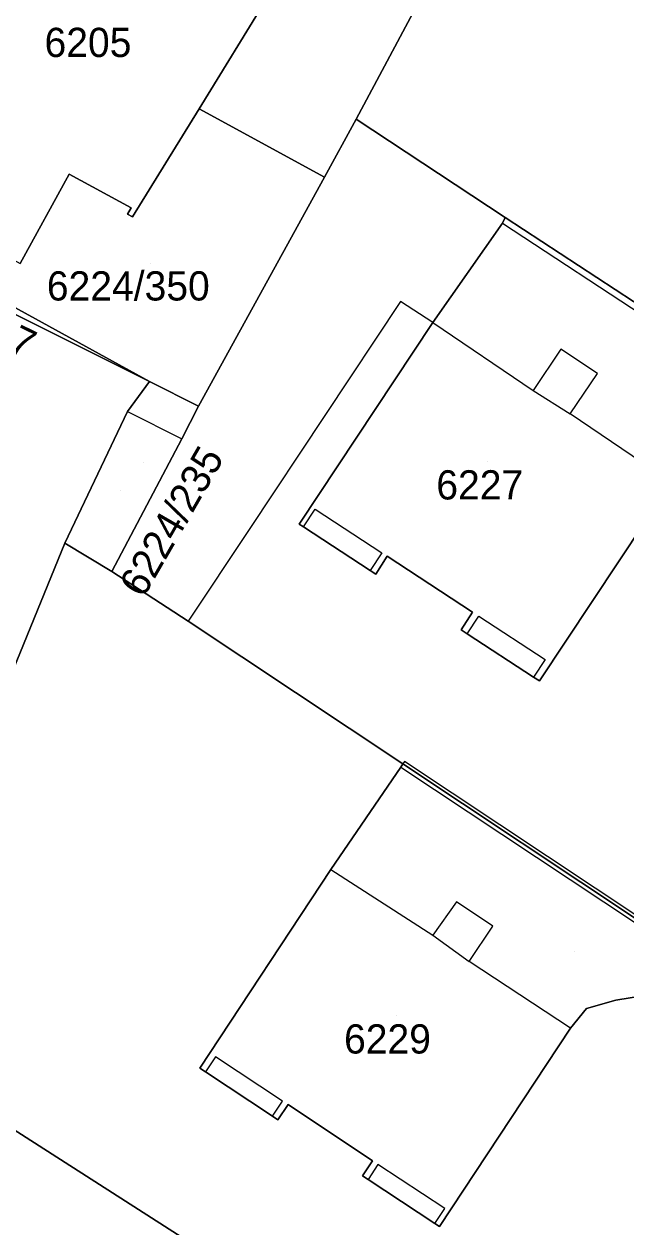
# Model space of a CAD drawing. Extents: x -266199 to -261993, y -1239047 to -1235108.
# Drawn here: x -263819.5 to -263778.3, y -1236358.3 to -1236276 of the extents above; entities that cross this region are included whole.
import ezdxf

# ---------------------------------------------------------------- set-up
doc = ezdxf.new("R2010")
doc.units = 0
for name, color, linetype in [('body_kn', 7, 'Continuous'), ('kladpar_druhypozemkov', 7, 'Continuous'), ('kladpar_hranice', 7, 'Continuous'), ('kladpar_parcelnecisla', 7, 'Continuous'), ('kladpar_plochy', 7, 'Continuous'), ('kladpar_sipky', 7, 'Continuous'), ('zappar_hrandruhpozemk', 7, 'Continuous')]:
    doc.layers.add(name, color=color, linetype=linetype)

msp = doc.modelspace()

# ---------------------------------------------------------------- linework, layer by layer
at = {"layer": 'body_kn'}
for p, q in [((-263807.51, -1236281.78), (-263807.51, -1236281.78)), ((-263796.75, -1236282.5), (-263796.75, -1236282.5)), ((-263796.75, -1236282.5), (-263796.75, -1236282.5)), ((-263816.41, -1236286.25), (-263816.41, -1236286.25)), ((-263798.93, -1236286.46), (-263798.93, -1236286.46)), ((-263798.93, -1236286.46), (-263798.93, -1236286.46)), ((-263812.41, -1236289), (-263812.41, -1236289)), ((-263812.17, -1236288.56), (-263812.17, -1236288.56)), ((-263812.06, -1236289.19), (-263812.06, -1236289.19)), ((-263786.56, -1236289.23), (-263786.56, -1236289.23)), ((-263786.73, -1236289.62), (-263786.73, -1236289.62)), ((-263786.73, -1236289.62), (-263786.73, -1236289.62)), ((-263793.71, -1236294.97), (-263793.71, -1236294.97)), ((-263791.51, -1236296.42), (-263791.51, -1236296.42)), ((-263791.51, -1236296.42), (-263791.51, -1236296.42)), ((-263782.73, -1236298.23), (-263782.73, -1236298.23)), ((-263780.23, -1236299.91), (-263780.23, -1236299.91)), ((-263810.9, -1236300.45), (-263810.9, -1236300.45)), ((-263810.9, -1236300.45), (-263810.9, -1236300.45)), ((-263784.64, -1236301.08), (-263784.64, -1236301.08)), ((-263784.64, -1236301.08), (-263784.64, -1236301.08)), ((-263812.41, -1236302.51), (-263812.41, -1236302.51)), ((-263812.41, -1236302.51), (-263812.41, -1236302.51)), ((-263807.56, -1236302.15), (-263807.56, -1236302.15)), ((-263782.09, -1236302.67), (-263782.09, -1236302.67)), ((-263808.68, -1236304.39), (-263808.68, -1236304.39)), ((-263799.56, -1236309.2), (-263799.56, -1236309.2)), ((-263804.09, -1236310.59), (-263804.09, -1236310.59)), ((-263800.66, -1236310.21), (-263800.66, -1236310.21)), ((-263800.35, -1236310.41), (-263800.35, -1236310.41)), ((-263816.7, -1236311.53), (-263816.7, -1236311.53)), ((-263795, -1236312.18), (-263795, -1236312.18)), ((-263794.62, -1236312.42), (-263794.62, -1236312.42)), ((-263813.49, -1236313.46), (-263813.49, -1236313.46)), ((-263813.49, -1236313.46), (-263813.49, -1236313.46)), ((-263795.79, -1236313.39), (-263795.79, -1236313.39)), ((-263795.79, -1236313.39), (-263795.79, -1236313.39)), ((-263795.41, -1236313.64), (-263795.41, -1236313.64)), ((-263788.78, -1236316.24), (-263788.78, -1236316.24)), ((-263788.36, -1236316.51), (-263788.36, -1236316.51)), ((-263808.25, -1236316.86), (-263808.25, -1236316.86)), ((-263789.57, -1236317.45), (-263789.57, -1236317.45)), ((-263789.15, -1236317.72), (-263789.15, -1236317.72)), ((-263783.81, -1236319.48), (-263783.81, -1236319.48)), ((-263784.6, -1236320.69), (-263784.6, -1236320.69)), ((-263784.6, -1236320.69), (-263784.6, -1236320.69)), ((-263784.21, -1236320.95), (-263784.21, -1236320.95)), ((-263793.69, -1236326.86), (-263793.69, -1236326.86)), ((-263793.69, -1236326.86), (-263793.69, -1236326.86)), ((-263793.55, -1236326.63), (-263793.55, -1236326.63)), ((-263793.45, -1236326.46), (-263793.45, -1236326.46)), ((-263798.48, -1236333.85), (-263798.48, -1236333.85)), ((-263798.48, -1236333.85), (-263798.48, -1236333.85)), ((-263789.89, -1236336.08), (-263789.89, -1236336.08)), ((-263787.4, -1236337.73), (-263787.4, -1236337.73)), ((-263791.51, -1236338.36), (-263791.51, -1236338.36)), ((-263791.51, -1236338.36), (-263791.51, -1236338.36)), ((-263789.01, -1236340.16), (-263789.01, -1236340.16)), ((-263789.01, -1236340.16), (-263789.01, -1236340.16)), ((-263778.97, -1236342.8), (-263778.97, -1236342.8)), ((-263780.98, -1236343.37), (-263780.98, -1236343.37)), ((-263782.08, -1236344.73), (-263782.08, -1236344.73)), ((-263782.08, -1236344.73), (-263782.08, -1236344.73)), ((-263806.39, -1236346.68), (-263806.39, -1236346.68)), ((-263807.45, -1236347.47), (-263807.45, -1236347.47)), ((-263807.07, -1236347.72), (-263807.07, -1236347.72)), ((-263807.07, -1236347.72), (-263807.07, -1236347.72)), ((-263801.8, -1236349.71), (-263801.8, -1236349.71)), ((-263801.42, -1236349.95), (-263801.42, -1236349.95)), ((-263802.49, -1236350.75), (-263802.49, -1236350.75)), ((-263802.11, -1236351), (-263802.11, -1236351)), ((-263795.63, -1236353.8), (-263795.63, -1236353.8)), ((-263795.26, -1236354.05), (-263795.26, -1236354.05)), ((-263796.31, -1236354.83), (-263796.31, -1236354.83)), ((-263795.94, -1236355.08), (-263795.94, -1236355.08)), ((-263795.94, -1236355.08), (-263795.94, -1236355.08)), ((-263790.69, -1236357.07), (-263790.69, -1236357.07)), ((-263791.36, -1236358.1), (-263791.36, -1236358.1)), ((-263791.04, -1236358.31), (-263791.04, -1236358.31))]:
    msp.add_line(p, q, dxfattribs=at)
at = {"layer": 'kladpar_druhypozemkov'}
for p, q in [((-263810.83, -1236292.41), (-263810.83, -1236292.41)), ((-263787.74, -1236305.93), (-263787.74, -1236305.93)), ((-263812.92, -1236307.92), (-263812.92, -1236307.92)), ((-263781.77, -1236339.49), (-263781.77, -1236339.49)), ((-263794.01, -1236343.86), (-263794.01, -1236343.86))]:
    msp.add_line(p, q, dxfattribs=at)
at = {"layer": 'kladpar_hranice'}
for p, q in [((-263810.9, -1236300.45), (-263846.39, -1236282.72)), ((-263800.35, -1236310.41), (-263795.79, -1236313.39)), ((-263795.79, -1236313.39), (-263800.35, -1236310.41)), ((-263789.15, -1236317.72), (-263784.6, -1236320.69)), ((-263784.6, -1236320.69), (-263789.15, -1236317.72)), ((-263807.07, -1236347.72), (-263802.49, -1236350.75)), ((-263802.49, -1236350.75), (-263807.07, -1236347.72)), ((-263795.94, -1236355.08), (-263791.36, -1236358.1)), ((-263791.36, -1236358.1), (-263795.94, -1236355.08))]:
    msp.add_line(p, q, dxfattribs=at)
for points in [[(-263796.75, -1236282.5), (-263788.43, -1236266.89), (-263783.8, -1236258.27), (-263775.41, -1236246.66), (-263764.02, -1236230.89), (-263749.03, -1236253.95), (-263754.73, -1236264.56), (-263764.22, -1236259.99), (-263768.57, -1236267.16), (-263777.59, -1236280.96), (-263777.22, -1236281.21)], [(-263798.93, -1236286.46), (-263807.51, -1236281.78), (-263802.82, -1236274.14), (-263803.17, -1236273.91), (-263803.44, -1236274.35), (-263807.6, -1236272.02), (-263804.25, -1236265.93), (-263807.98, -1236263.87), (-263806.58, -1236261.49), (-263804.15, -1236257.35), (-263788.43, -1236266.89), (-263796.75, -1236282.5), (-263798.93, -1236286.46)], [(-263822.7, -1236271.16), (-263819.28, -1236264.87), (-263818.87, -1236265.09), (-263819.18, -1236265.67), (-263814.21, -1236268.37), (-263810.89, -1236262.27), (-263807.98, -1236263.87), (-263804.25, -1236265.93), (-263807.6, -1236272.02), (-263803.44, -1236274.35), (-263803.17, -1236273.91), (-263802.82, -1236274.14), (-263807.51, -1236281.78), (-263812.06, -1236289.19), (-263812.41, -1236289), (-263812.17, -1236288.56), (-263816.41, -1236286.25), (-263819.76, -1236292.38)], [(-263761.6, -1236291.64), (-263761.29, -1236291.85), (-263752.18, -1236278.07), (-263747.42, -1236267.12), (-263740.96, -1236268.86), (-263740.08, -1236270.96), (-263745.67, -1236293.91), (-263749.42, -1236308.46), (-263754.6, -1236309.83), (-263770.22, -1236299.9), (-263786.56, -1236289.23), (-263796.75, -1236282.5)], [(-263846.39, -1236282.72), (-263845.64, -1236281.4), (-263832.11, -1236288.82), (-263824.25, -1236293.13), (-263810.9, -1236300.45)], [(-263824.25, -1236293.13), (-263822.95, -1236290.64), (-263819.76, -1236292.38), (-263816.41, -1236286.25), (-263812.17, -1236288.56), (-263812.41, -1236289), (-263812.06, -1236289.19), (-263807.51, -1236281.78), (-263798.93, -1236286.46), (-263807.56, -1236302.15), (-263810.9, -1236300.45), (-263824.25, -1236293.13)], [(-263857.92, -1236304.91), (-263846.39, -1236282.72), (-263810.9, -1236300.45)], [(-263813.49, -1236313.46), (-263808.68, -1236304.39), (-263807.56, -1236302.15), (-263798.93, -1236286.46), (-263796.75, -1236282.5), (-263786.56, -1236289.23), (-263786.73, -1236289.62), (-263791.51, -1236296.42), (-263800.66, -1236310.21), (-263800.35, -1236310.41)], [(-263791.51, -1236296.42), (-263786.73, -1236289.62), (-263786.56, -1236289.23), (-263770.22, -1236299.9), (-263754.6, -1236309.83), (-263749.42, -1236308.46), (-263752.65, -1236320.75), (-263756.67, -1236313.9), (-263770.56, -1236305.23), (-263772.57, -1236305.43), (-263774.56, -1236306.29), (-263775.19, -1236307.37), (-263784.21, -1236320.95), (-263784.6, -1236320.69)], [(-263800.35, -1236310.41), (-263800.66, -1236310.21), (-263791.51, -1236296.42)], [(-263810.9, -1236300.45), (-263812.41, -1236302.51), (-263816.7, -1236311.53), (-263821.43, -1236323.05), (-263857.92, -1236304.91)], [(-263813.49, -1236313.46), (-263816.7, -1236311.53), (-263812.41, -1236302.51), (-263810.9, -1236300.45), (-263807.56, -1236302.15), (-263808.68, -1236304.39), (-263813.49, -1236313.46)], [(-263784.6, -1236320.69), (-263784.21, -1236320.95), (-263775.19, -1236307.37), (-263774.56, -1236306.29), (-263772.57, -1236305.43), (-263770.56, -1236305.23), (-263756.67, -1236313.9), (-263752.65, -1236320.75), (-263759.07, -1236345.06), (-263763.77, -1236346.42), (-263777.28, -1236337.44), (-263793.55, -1236326.63), (-263808.25, -1236316.86), (-263813.49, -1236313.46)], [(-263762.85, -1236355.68), (-263773.1, -1236380.05), (-263777.22, -1236379.94), (-263805.43, -1236361.14), (-263826.5, -1236347.64), (-263830.59, -1236345.33), (-263821.43, -1236323.05), (-263816.7, -1236311.53), (-263813.49, -1236313.46), (-263808.25, -1236316.86), (-263793.55, -1236326.63), (-263793.69, -1236326.86), (-263798.48, -1236333.85), (-263807.45, -1236347.47), (-263807.07, -1236347.72)], [(-263795.79, -1236313.39), (-263795.41, -1236313.64), (-263794.62, -1236312.42), (-263788.78, -1236316.24), (-263789.57, -1236317.45), (-263789.15, -1236317.72)], [(-263789.15, -1236317.72), (-263789.57, -1236317.45), (-263788.78, -1236316.24), (-263794.62, -1236312.42), (-263795.41, -1236313.64), (-263795.79, -1236313.39)], [(-263807.07, -1236347.72), (-263807.45, -1236347.47), (-263798.48, -1236333.85), (-263793.69, -1236326.86), (-263793.55, -1236326.63), (-263777.28, -1236337.44), (-263763.77, -1236346.42), (-263759.07, -1236345.06)], [(-263791.36, -1236358.1), (-263791.04, -1236358.31), (-263782.08, -1236344.73), (-263780.98, -1236343.37), (-263778.97, -1236342.8), (-263777.02, -1236342.49), (-263766.07, -1236349.83), (-263762.85, -1236355.68)], [(-263759.07, -1236345.06), (-263762.85, -1236355.68), (-263766.07, -1236349.83), (-263777.02, -1236342.49), (-263778.97, -1236342.8), (-263780.98, -1236343.37), (-263782.08, -1236344.73), (-263791.04, -1236358.31), (-263791.36, -1236358.1)], [(-263776.86, -1236388.45), (-263788.06, -1236414.17), (-263791.19, -1236414.68), (-263808.89, -1236402.95), (-263822.61, -1236393.49), (-263838.12, -1236382.81), (-263842.53, -1236380.41), (-263835.4, -1236365.83), (-263826.5, -1236347.64), (-263805.43, -1236361.14), (-263810.25, -1236368.33), (-263819.14, -1236381.6), (-263818.77, -1236381.85)], [(-263802.49, -1236350.75), (-263802.11, -1236351), (-263801.42, -1236349.95), (-263795.63, -1236353.8), (-263796.31, -1236354.83), (-263795.94, -1236355.08)], [(-263795.94, -1236355.08), (-263796.31, -1236354.83), (-263795.63, -1236353.8), (-263801.42, -1236349.95), (-263802.11, -1236351), (-263802.49, -1236350.75)]]:
    msp.add_lwpolyline(points, dxfattribs=at)
at = {"layer": 'kladpar_plochy'}
for points in [[(-263798.93, -1236286.46), (-263807.51, -1236281.78), (-263802.82, -1236274.14), (-263803.17, -1236273.91), (-263803.44, -1236274.35), (-263807.6, -1236272.02), (-263804.25, -1236265.93), (-263807.98, -1236263.87), (-263806.58, -1236261.49), (-263804.15, -1236257.35), (-263788.43, -1236266.89), (-263796.75, -1236282.5)], [(-263846.39, -1236282.72), (-263845.64, -1236281.4), (-263832.11, -1236288.82), (-263824.25, -1236293.13), (-263810.9, -1236300.45)], [(-263824.25, -1236293.13), (-263822.95, -1236290.64), (-263819.76, -1236292.38), (-263816.41, -1236286.25), (-263812.17, -1236288.56), (-263812.41, -1236289), (-263812.06, -1236289.19), (-263807.51, -1236281.78), (-263798.93, -1236286.46), (-263807.56, -1236302.15), (-263810.9, -1236300.45)], [(-263857.92, -1236304.91), (-263846.39, -1236282.72), (-263810.9, -1236300.45), (-263812.41, -1236302.51), (-263816.7, -1236311.53), (-263821.43, -1236323.05)], [(-263791.51, -1236296.42), (-263786.73, -1236289.62), (-263786.56, -1236289.23), (-263770.22, -1236299.9), (-263754.6, -1236309.83), (-263749.42, -1236308.46), (-263752.65, -1236320.75), (-263756.67, -1236313.9), (-263770.56, -1236305.23), (-263772.57, -1236305.43), (-263774.56, -1236306.29), (-263775.19, -1236307.37), (-263784.21, -1236320.95), (-263784.6, -1236320.69), (-263789.15, -1236317.72), (-263789.57, -1236317.45), (-263788.78, -1236316.24), (-263794.62, -1236312.42), (-263795.41, -1236313.64), (-263795.79, -1236313.39), (-263800.35, -1236310.41), (-263800.66, -1236310.21)], [(-263813.49, -1236313.46), (-263816.7, -1236311.53), (-263812.41, -1236302.51), (-263810.9, -1236300.45), (-263807.56, -1236302.15), (-263808.68, -1236304.39)], [(-263759.07, -1236345.06), (-263762.85, -1236355.68), (-263766.07, -1236349.83), (-263777.02, -1236342.49), (-263778.97, -1236342.8), (-263780.98, -1236343.37), (-263782.08, -1236344.73), (-263791.04, -1236358.31), (-263791.36, -1236358.1), (-263795.94, -1236355.08), (-263796.31, -1236354.83), (-263795.63, -1236353.8), (-263801.42, -1236349.95), (-263802.11, -1236351), (-263802.49, -1236350.75), (-263807.07, -1236347.72), (-263807.45, -1236347.47), (-263798.48, -1236333.85), (-263793.69, -1236326.86), (-263793.55, -1236326.63), (-263777.28, -1236337.44), (-263763.77, -1236346.42)]]:
    msp.add_lwpolyline(points, close=True, dxfattribs=at)
for points in [[(-263822.7, -1236271.16), (-263819.28, -1236264.87), (-263818.87, -1236265.09), (-263819.18, -1236265.67), (-263814.21, -1236268.37), (-263810.89, -1236262.27), (-263807.98, -1236263.87), (-263804.25, -1236265.93), (-263807.6, -1236272.02), (-263803.44, -1236274.35), (-263803.17, -1236273.91), (-263802.82, -1236274.14), (-263807.51, -1236281.78), (-263812.06, -1236289.19), (-263812.41, -1236289), (-263812.17, -1236288.56), (-263816.41, -1236286.25), (-263819.76, -1236292.38)], [(-263740.08, -1236270.96), (-263745.67, -1236293.91), (-263749.42, -1236308.46), (-263754.6, -1236309.83), (-263770.22, -1236299.9), (-263786.56, -1236289.23), (-263796.75, -1236282.5), (-263788.43, -1236266.89)], [(-263777.28, -1236337.44), (-263793.55, -1236326.63), (-263808.25, -1236316.86), (-263813.49, -1236313.46), (-263808.68, -1236304.39), (-263807.56, -1236302.15), (-263798.93, -1236286.46), (-263796.75, -1236282.5), (-263786.56, -1236289.23), (-263786.73, -1236289.62), (-263791.51, -1236296.42), (-263800.66, -1236310.21), (-263800.35, -1236310.41), (-263795.79, -1236313.39), (-263795.41, -1236313.64), (-263794.62, -1236312.42), (-263788.78, -1236316.24), (-263789.57, -1236317.45), (-263789.15, -1236317.72), (-263784.6, -1236320.69), (-263784.21, -1236320.95), (-263775.19, -1236307.37)], [(-263821.43, -1236323.05), (-263816.7, -1236311.53), (-263813.49, -1236313.46), (-263808.25, -1236316.86), (-263793.55, -1236326.63), (-263793.69, -1236326.86), (-263798.48, -1236333.85), (-263807.45, -1236347.47), (-263807.07, -1236347.72), (-263802.49, -1236350.75), (-263802.11, -1236351), (-263801.42, -1236349.95), (-263795.63, -1236353.8), (-263796.31, -1236354.83), (-263795.94, -1236355.08), (-263791.36, -1236358.1), (-263791.04, -1236358.31), (-263782.08, -1236344.73), (-263780.98, -1236343.37), (-263778.97, -1236342.8), (-263777.02, -1236342.49), (-263766.07, -1236349.83), (-263762.85, -1236355.68), (-263773.1, -1236380.05)], [(-263826.5, -1236347.64), (-263805.43, -1236361.14)], [(-263805.43, -1236361.14), (-263826.5, -1236347.64)]]:
    msp.add_lwpolyline(points, dxfattribs=at)
at = {"layer": 'kladpar_sipky'}
msp.add_line((-263811.3, -1236306.03), (-263811.3, -1236306.03), dxfattribs=at)
at = {"layer": 'zappar_hrandruhpozemk'}
for p, q in [((-263786.73, -1236289.62), (-263770.53, -1236300.26)), ((-263793.71, -1236294.97), (-263804.09, -1236310.59)), ((-263791.51, -1236296.42), (-263793.71, -1236294.97)), ((-263791.51, -1236296.42), (-263784.64, -1236301.08)), ((-263782.73, -1236298.23), (-263784.64, -1236301.08)), ((-263780.23, -1236299.91), (-263782.73, -1236298.23)), ((-263812.41, -1236302.51), (-263808.68, -1236304.39)), ((-263775.19, -1236307.37), (-263782.09, -1236302.67)), ((-263800.35, -1236310.41), (-263799.56, -1236309.2)), ((-263799.56, -1236309.2), (-263795, -1236312.18)), ((-263804.09, -1236310.59), (-263808.25, -1236316.86)), ((-263795, -1236312.18), (-263795.79, -1236313.39)), ((-263789.15, -1236317.72), (-263788.36, -1236316.51)), ((-263788.36, -1236316.51), (-263783.81, -1236319.48)), ((-263783.81, -1236319.48), (-263784.6, -1236320.69)), ((-263793.69, -1236326.86), (-263777.48, -1236337.61)), ((-263793.45, -1236326.46), (-263793.55, -1236326.63)), ((-263777.12, -1236337.3), (-263793.45, -1236326.46)), ((-263798.48, -1236333.85), (-263791.51, -1236338.36)), ((-263791.51, -1236338.36), (-263789.01, -1236340.16)), ((-263782.08, -1236344.73), (-263789.01, -1236340.16)), ((-263806.39, -1236346.68), (-263807.07, -1236347.72)), ((-263801.8, -1236349.71), (-263806.39, -1236346.68)), ((-263802.49, -1236350.75), (-263801.8, -1236349.71)), ((-263795.26, -1236354.05), (-263795.94, -1236355.08)), ((-263790.69, -1236357.07), (-263795.26, -1236354.05)), ((-263791.36, -1236358.1), (-263790.69, -1236357.07))]:
    msp.add_line(p, q, dxfattribs=at)
for points in [[(-263784.64, -1236301.08), (-263782.09, -1236302.67), (-263780.23, -1236299.91)], [(-263789.01, -1236340.16), (-263787.4, -1236337.73), (-263789.89, -1236336.08), (-263791.51, -1236338.36)]]:
    msp.add_lwpolyline(points, dxfattribs=at)

# ---------------------------------------------------------------- texts
at = {"layer": 'kladpar_parcelnecisla'}
for s, p in [('6205', (-263818.093, -1236278.24)), ('6224/350', (-263817.934, -1236294.91)), ('6227', (-263791.266, -1236308.53)), ('6229', (-263797.583, -1236346.46))]:
    msp.add_text(s, height=2, dxfattribs=at).set_placement(p)
for s, rotation, p in [('6224/287', 334, (-263829.365, -1236294.065)), ('6224/235', 60, (-263811.329, -1236315.336))]:
    msp.add_text(s, height=2, rotation=rotation, dxfattribs=at).set_placement(p)

doc.saveas('drawing.dxf')
